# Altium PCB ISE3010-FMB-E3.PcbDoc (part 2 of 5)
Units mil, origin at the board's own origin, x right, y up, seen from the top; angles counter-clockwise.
Board outline 7874.02 x 2362.2 mil, 4 copper layers (Top Layer, MidLayer1, MidLayer2, Bottom Layer), stack 55.6 mil thick; 507 components, 331 nets, 1707 pads, 610 vias.
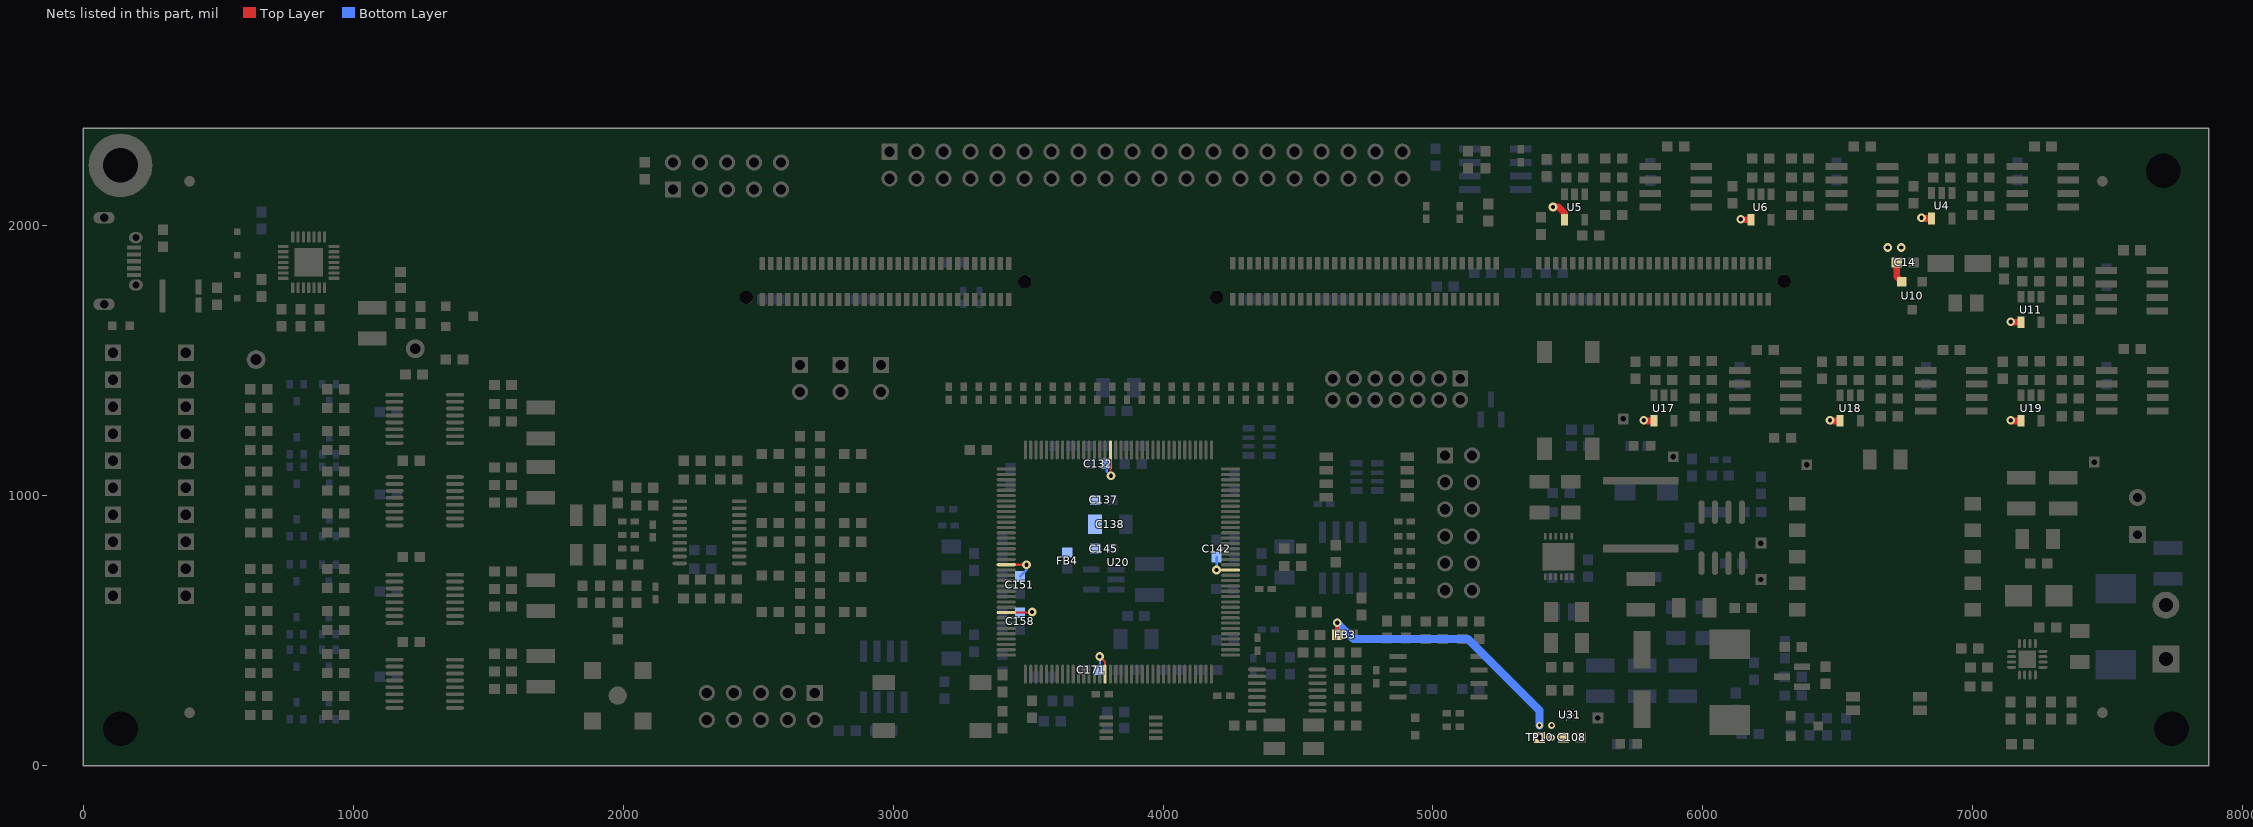
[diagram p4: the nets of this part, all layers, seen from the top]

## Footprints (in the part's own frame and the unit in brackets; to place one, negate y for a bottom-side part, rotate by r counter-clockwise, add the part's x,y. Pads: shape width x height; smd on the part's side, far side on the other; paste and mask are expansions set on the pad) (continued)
HE_800x1150 [mm] "NICHICON"
  rect 1.6x1.6 hole 0.838: 1(-1.75,0)
  round 1.6 hole 0.838: 2(1.75,0)
  silkscreen extent -4.25,-4.25 4.25,4.25, body extent -4.22,-4.24 4.24,4.24, height 11.51
HEADER_2X5 [mil]
  rect 60x60 hole 38: 1(0,0)
  round 60 hole 38: 2(0,100) 3(100,0) 4(100,100) 5(200,0) 6(200,100) 7(300,0) 8(300,100) 9(400,0) 10(400,100)
  silkscreen extent -50,-50 450,150
HEADER_2X6 [mil]
  rect 60x60 hole 38: 1(0,0)
  round 60 hole 38: 2(0,100) 3(100,0) 4(100,100) 5(200,0) 6(200,100) 7(300,0) 8(300,100) 9(400,0) 10(400,100) 11(500,0) 12(500,100)
  silkscreen extent -65,-65 565,165
HSEC8-130-01-L-DV-A [mm]
  rect 0.5x1.2 smd: 121(11.6,1.7) 122(11.6,-1.7) 123(10.8,1.7) 124(10.8,-1.7) 125(10,1.7) 126(10,-1.7) 127(9.2,1.7) 128(9.2,-1.7) 129(8.4,1.7) 130(8.4,-1.7) 131(7.6,1.7) 132(7.6,-1.7) 133(6.8,1.7) 134(6.8,-1.7) 135(6,1.7) 136(6,-1.7) 137(5.2,1.7) 138(5.2,-1.7) 139(4.4,1.7) 140(4.4,-1.7) 141(3.6,1.7) 142(3.6,-1.7) 143(2.8,1.7) 144(2.8,-1.7) 145(2,1.7) 146(2,-1.7) 147(1.2,1.7) 148(1.2,-1.7) 149(0.4,1.7) 150(0.4,-1.7) 151(-0.4,1.7) 152(-0.4,-1.7) 153(-1.2,1.7) 154(-1.2,-1.7) 155(-2,1.7) 156(-2,-1.7) 157(-2.8,1.7) 158(-2.8,-1.7) 159(-3.6,1.7) 160(-3.6,-1.7) 161(-4.4,1.7) 162(-4.4,-1.7) 163(-5.2,1.7) 164(-5.2,-1.7) 165(-6,1.7) 166(-6,-1.7) 167(-6.8,1.7) 168(-6.8,-1.7) 169(-7.6,1.7) 170(-7.6,-1.7) 171(-8.4,1.7) 172(-8.4,-1.7) 173(-9.2,1.7) 174(-9.2,-1.7) 175(-10,1.7) 176(-10,-1.7) 177(-10.8,1.7) 178(-10.8,-1.7) 179(-11.6,1.7) 180(-11.6,-1.7)
  round 1.27 hole 1.27 unplated mask+0.127: 181(13.1,0) 182(-13.1,-1.5)
  silkscreen extent -14.3,-3.55 14.3,3.5
HSEC8-160-01-L-DV-A-L [mm] "CONN HIGH SPD CARD EDGE 120 POS"
  rect 0.5x1.2 smd: 1(25.2,1.7) 2(25.2,-1.7) 3(24.4,1.7) 4(24.4,-1.7) 5(23.6,1.7) 6(23.6,-1.7) 7(22.8,1.7) 8(22.8,-1.7) 9(22,1.7) 10(22,-1.7) 11(21.2,1.7) 12(21.2,-1.7) 13(20.4,1.7) 14(20.4,-1.7) 15(19.6,1.7) 16(19.6,-1.7) 17(18.8,1.7) 18(18.8,-1.7) 19(18,1.7) 20(18,-1.7) 21(17.2,1.7) 22(17.2,-1.7) 23(16.4,1.7) 24(16.4,-1.7) 25(15.6,1.7) 26(15.6,-1.7) 27(14.8,1.7) 28(14.8,-1.7) 29(14,1.7) 30(14,-1.7) 31(13.2,1.7) 32(13.2,-1.7) 33(12.4,1.7) 34(12.4,-1.7) 35(11.6,1.7) 36(11.6,-1.7) 37(10.8,1.7) 38(10.8,-1.7) 39(10,1.7) 40(10,-1.7) 41(9.2,1.7) 42(9.2,-1.7) 43(8.4,1.7) 44(8.4,-1.7) 45(7.6,1.7) 46(7.6,-1.7) 47(6.8,1.7) 48(6.8,-1.7) 49(6,1.7) 50(6,-1.7) 51(5.2,1.7) 52(5.2,-1.7) 53(4.4,1.7) 54(4.4,-1.7) 55(3.6,1.7) 56(3.6,-1.7) 57(-0.4,1.7) 58(-0.4,-1.7) 59(-1.2,1.7) 60(-1.2,-1.7) 61(-2,1.7) 62(-2,-1.7) 63(-2.8,1.7) 64(-2.8,-1.7) 65(-3.6,1.7) 66(-3.6,-1.7) 67(-4.4,1.7) 68(-4.4,-1.7) 69(-5.2,1.7) 70(-5.2,-1.7) 71(-6,1.7) 72(-6,-1.7) 73(-6.8,1.7) 74(-6.8,-1.7) 75(-7.6,1.7) 76(-7.6,-1.7) 77(-8.4,1.7) 78(-8.4,-1.7) 79(-9.2,1.7) 80(-9.2,-1.7) 81(-10,1.7) 82(-10,-1.7) 83(-10.8,1.7) 84(-10.8,-1.7) 85(-11.6,1.7) 86(-11.6,-1.7) 87(-12.4,1.7) 88(-12.4,-1.7) 89(-13.2,1.7) 90(-13.2,-1.7) 91(-14,1.7) 92(-14,-1.7) 93(-14.8,1.7) 94(-14.8,-1.7) 95(-15.6,1.7) 96(-15.6,-1.7) 97(-16.4,1.7) 98(-16.4,-1.7) 99(-17.2,1.7) 100(-17.2,-1.7) 101(-18,1.7) 102(-18,-1.7) 103(-18.8,1.7) 104(-18.8,-1.7) 105(-19.6,1.7) 106(-19.6,-1.7) 107(-20.4,1.7) 108(-20.4,-1.7) 109(-21.2,1.7) 110(-21.2,-1.7) 111(-22,1.7) 112(-22,-1.7) 113(-22.8,1.7) 114(-22.8,-1.7) 115(-23.6,1.7) 116(-23.6,-1.7) 117(-24.4,1.7) 118(-24.4,-1.7) 119(-25.2,1.7) 120(-25.2,-1.7)
  round 1.27 hole 1.27 unplated mask+0.127: 121(-26.7,-1.5) 122(26.7,0)
  silkscreen extent -35.4,-3.56 35.4,3.5
Label_650x200 [mil] "Thermal Transfer Label"
  silkscreen extent -325,-100 325,100, body extent -326,-101 326,101, height 1
LED0603AA [mil]
  rect 32x32 smd: 1(-32.48,0) 2(32.48,0)
  silkscreen extent -132,-25 8,25
LED_0603 [mm] "LED, HIGHBRIGHT, BLUE, SMT0603"
  rect 0.9x0.9 smd paste+0: 1(-0.8,0) 2(0.8,0)
  silkscreen extent -0.81,-0.76 1.65,0.76, body extent -0.8,-0.4 0.8,0.4, height 0.8
MF05A_N [mm] "SOT23, 5-Leads, Body 2.9x1.6mm, Pitch 0.95mm, Lead Span 2.8mm, IPC Medium Density"
  rect 1.1x0.65 smd: 1(-1.2,0.95) 2(-1.2,0) 3(-1.2,-0.95) 4(1.2,-0.95) 5(1.2,0.95)
  silkscreen extent -1.32,-1.55 0.25,1.8, body extent -0.9,-1.55 0.9,1.55, height 1.19
MH3.2 [mm]
  round 6 / inner round 3.607 / far side round 6 hole 3.251: 1(0,0)
  silkscreen extent -3.25,-3.25 3.25,3.25
MH3.2_NPTH [mil]
  round 20 / inner round 142 / far side round 20 hole 128 unplated mask+65: 1(0,0)
  silkscreen extent -120,-120 120,120
MSS7341 [mil] "Coilcraft recommended land pattern Document 383-2 1/3/11"
  rect 28.54x280 smd: 1(-125.49,0) 2(125.49,0)
  Top Layer region: -41.34,-139.76 -41.34,-101.16 -41.33,-101.13 -82.83,-71.24 -106.18,-25.72 -106.25,25.43 -83.02,71.01 -41.6,101.02 -41.6,101.02 -41.34,101.02 -41.34,139.76 -139.76,139.76 -139.76,-139.76
  Top Layer region: 41.34,-139.76 41.34,-101.16 41.33,-101.13 82.83,-71.24 106.18,-25.72 106.25,25.43 83.02,71.01 41.6,101.02 41.6,101.02 41.34,101.02 41.34,139.76 139.76,139.76 139.76,-139.76
  silkscreen extent -152,-154 151,154, body extent -149,-149 149,149, height 162
"POLYZEN 4 x 4 SMD" [mm] "POLYZEN 4 x 4 SMD"
  rect 0.56x3.1 smd: 1(-1.7,0)
  rect 0.56x1.4 smd: 2(1.7,0.85) 3(1.7,-0.85)
  silkscreen extent -2.3,-2.3 2.3,2.3
PW0014A_N [mm] "TSOP, 14-Leads, Body 5x4.4mm, Pitch 0.65mm, IPC Medium Density"
  oval 1.7x0.35 smd: 1(-2.85,1.95) 2(-2.85,1.3) 3(-2.85,0.65) 4(-2.85,0) 5(-2.85,-0.65) 6(-2.85,-1.3) 7(-2.85,-1.95) 8(2.85,-1.95) 9(2.85,-1.3) 10(2.85,-0.65) 11(2.85,0) 12(2.85,0.65) 13(2.85,1.3) 14(2.85,1.95)
  silkscreen extent -1.7,-2.55 1.7,2.29, body extent -3.21,-2.5 3.21,2.5, height 0.98
PW0016A_N [mm] "TSOP, 16-Leads, Body 5x4.4mm, Pitch 0.65mm, IPC Medium Density"
  oval 1.7x0.35 smd: 1(-2.85,2.275) 2(-2.85,1.625) 3(-2.85,0.975) 4(-2.85,0.325) 5(-2.85,-0.325) 6(-2.85,-0.975) 7(-2.85,-1.625) 8(-2.85,-2.275) 9(2.85,-2.275) 10(2.85,-1.625) 11(2.85,-0.975) 12(2.85,-0.325) 13(2.85,0.325) 14(2.85,0.975) 15(2.85,1.625) 16(2.85,2.275)
  silkscreen extent -1.5,-2.55 1.5,2.55, body extent -3.21,-2.5 3.21,2.5, height 0.98
PW0020A_L [mm] "TSOP, 20-Leads, Body 6.5x4.4mm, Pitch 0.65mm, IPC High Density"
  oval 1.4x0.35 smd: 1(-2.8,2.925) 2(-2.8,2.275) 3(-2.8,1.625) 4(-2.8,0.975) 5(-2.8,0.325) 6(-2.8,-0.325) 7(-2.8,-0.975) 8(-2.8,-1.625) 9(-2.8,-2.275) 10(-2.8,-2.925) 11(2.8,-2.925) 12(2.8,-2.275) 13(2.8,-1.625) 14(2.8,-0.975) 15(2.8,-0.325) 16(2.8,0.325) 17(2.8,0.975) 18(2.8,1.625) 19(2.8,2.275) 20(2.8,2.925)
  silkscreen extent -2.92,-3.3 1.7,3.77, body extent -2.25,-3.3 2.25,3.3, height 1.2
QFN28[RHD] [mil]
  rrect50% 11.8x40 smd mask+2: 1(-59.1,-94) 2(-39.4,-94) 3(-19.7,-94) 4(0,-94) 5(19.7,-94) 6(39.4,-94) 7(59.1,-94) 15(59.1,94) 16(39.4,94) 17(19.7,94) 18(0,94) 19(-19.7,94) 20(-39.4,94) 21(-59.1,94)
  rrect50% 40x11.8 smd mask+2: 8(94,-59.1) 9(94,-39.4) 10(94,-19.7) 11(94,0) 12(94,19.7) 13(94,39.4) 14(94,59.1) 22(-94,59.1) 23(-94,39.4) 24(-94,19.7) 25(-94,0) 26(-94,-19.7) 27(-94,-39.4) 28(-94,-59.1)
  rect 106x106 smd mask+2.5: 29(0,0)
  silkscreen extent -164,-122 -139,-97
R-ACAS_0612 [mil]
  rect 25x45 smd mask+2.5: 1(-50.5,38.5) 2(-50.5,-38.5) 7(50.5,38.5) 8(50.5,-38.5)
  rect 17x45 smd mask+2.5: 3(-15.5,38.5) 4(-15.5,-38.5) 5(15.5,38.5) 6(15.5,-38.5)
RTE0016C [mm] "Texas Insturments"
  oval 0.85x0.28 smd mask+0.064: 1(-1.475,0.75) 2(-1.475,0.25) 3(-1.475,-0.25) 4(-1.475,-0.75) 9(1.475,-0.75) 10(1.475,-0.25) 11(1.475,0.25) 12(1.475,0.75)
  oval 0.28x0.85 smd mask+0.064: 5(-0.75,-1.475) 6(-0.25,-1.475) 7(0.25,-1.475) 8(0.75,-1.475) 13(0.75,1.475) 14(0.25,1.475) 15(-0.25,1.475) 16(-0.75,1.475)
  rect 1.66x1.66 smd paste-0.88 mask+0.089: 17(0,0)
  silkscreen extent -2.3,-1.78 1.78,1.78, body extent -1.58,-1.58 1.58,1.58, height 0.81
SM_RADIAL_6.3BMM [mm] "Nichicon 6.3x7.7"
  rect 3.5x1.6 smd: 1(-2.8,0) 2(2.8,0)
  silkscreen extent -3.4,-3.4 3.4,3.4, body extent -3.41,-3.41 3.41,3.41, height 8
SM_RADIAL_B [mm] "4 x 5.8mm:  Panasonic B"
  rect 2.5x1.6 smd: 1(-1.75,0) 2(1.75,0)
  silkscreen extent -2.24,-2.25 2.25,2.25, body extent -2.26,-2.26 2.26,2.26, height 6.1
SMA [mm] "Molded Diode, 2-Leads, Body 4.3x2.6mm, IPC Medium Density, based on OnSemi component dimensions and land pattern"
  rect 2x2 smd: 1(-2,0) 2(2,0)
  silkscreen extent -3.66,-1.57 2.79,1.57, body extent -2.6,-1.3 2.6,1.3, height 2.42
SMC [mil] "Molded Diode, 2-Leads, Body 6.9x5.8mm, IPC Medium Density, based on OnSemi component dimensions and land patterns"
  rect 110x150 smd: 1(-140.49,0) 2(140.49,0)
  silkscreen extent -221,-124 189,123, body extent -156,-116 156,116, height 91
SO8 [mil]
  rect 80x26 smd: 1(-95,75) 2(-95,25) 3(-95,-25) 4(-95,-75) 5(94,-75) 6(94,-25) 7(94,25) 8(94,75)
  silkscreen extent -160,115 -120,155
SO8W [mm] "SO8W P 7.62mm X 1.27"
  rect 1.6x0.5 smd: 1(0,0) 2(0,-1.27) 3(0,-2.54) 4(0,-3.81) 5(7.62,-3.81) 6(7.62,-2.54) 7(7.62,-1.27) 8(7.62,0)
  silkscreen extent -1.67,-4.44 8.7,0.72
sod-323 [mm] "NXP recommended land pattern"
  rect 0.6x0.6 smd: 1(-1.1,0) 2(1.1,0)
  silkscreen extent -2.06,-0.86 1.53,0.86, body extent -1.3,-0.67 1.3,0.68, height 1.1
SOP-4 [mm] "Vishay Half Pitch Mini-Flat Package"
  rect 1.3x0.9 smd: 1(-3.15,0.635) 2(-3.15,-0.635) 3(3.15,-0.635) 4(3.15,0.635)
  silkscreen extent -2.2,-1.41 2.2,1.39, body extent -3.5,-1.4 3.5,1.4, height 2.12
SOT-23#1 [mm] "SOT23, 3-Leads, Body 2.9x1.3mm, Pitch 0.95mm, Lead Span 2.5mm, IPC Medium Density"
  rect 1.5x0.6 smd: 1(-0.95,0.95) 2(-0.95,-0.95) 3(0.95,0)
  silkscreen extent 0.2,-1.5 0.7,1.5, body extent -1.16,-1.45 1.21,1.45, height 1
SOT-23#2 [mm]
  rect 0.889x0.889 smd: 1(-0.952,-1.334) 2(0.953,-1.333) 3(0,1.27)
SOT-323 [mm] "Zetex recommended land pattern.  March 2007"
  rect 0.8x0.6 smd: 1(-0.8,0.65) 2(-0.8,-0.65) 3(0.8,0)
  silkscreen extent -1.14,-1.22 1.09,1.49, body extent -1.13,-1.13 1.12,1.12, height 1.13
SW_218-4LPST [mil] "CTS Components"
  rect 50x30 smd: 1(-150,75) 2(-150,25) 3(-150,-25) 4(-150,-75) 5(150,-75) 6(150,-25) 7(150,25) 8(150,75)
  silkscreen extent -114,-123 114,123, body extent -166,-123 166,123, height 104
SW_FSM4JSMA [mm] "Alcoswitch"
  rect 1.4x2.1 smd: 1(2.25,4.55) 2(2.25,-4.55) 3(-2.25,4.55) 4(-2.25,-4.55)
  silkscreen extent -3,-3 3,3, body extent -3,-5 3,5, height 5.1
TB_2X5.1MM [mil]
  rect 100x100 hole 52: 1(0,0)
  round 100 hole 52: 2(200,0)
TI_Stacked_SolderMask_Small [mil]
  rect 0x0 smd paste-125 mask-125: 0(0,0)
  Top Layer region: 519 vertices and 0 holes, not listed, extent -418.39,-77.79 -237.37,98.14
  Top Layer region: -289.71,63.25 -290.44,63.25 -290.44,59.61 -291.16,59.61 -291.16,55.98 -291.89,55.98 -291.89,52.34 -292.62,52.34 -292.62,48.71 -293.34,48.71 -293.34,45.07 -294.07,45.07 -294.07,41.44 -294.8,41.44 -294.8,37.8 -295.53,37.8 -295.53,34.17 -296.25,34.17 -296.25,30.53 -296.98,30.53 -296.98,26.9 -297.71,26.9 -297.71,23.26 -298.43,23.26 -298.43,19.63 -299.16,19.63 -299.16,15.99 -299.89,15.99 -299.89,12.36 -300.61,12.36 -300.61,8.72 -301.34,8.72 -301.34,5.09 -302.07,5.09 -302.07,1.45 -302.8,1.45 -302.8,-2.18 -303.52,-2.18 -303.52,-5.82 -304.25,-5.82 -304.25,-9.45 -321.7,-9.45 -321.7,-7.27 -320.97,-7.27 -320.97,-3.64 -320.24,-3.64 -320.24,0 -319.52,0 -319.52,3.64 -318.79,3.64 -318.79,7.27 -318.06,7.27 -318.06,10.91 -317.34,10.91 -317.34,14.54 -316.61,14.54 -316.61,18.18 -315.88,18.18 -315.88,21.81 -315.15,21.81 -315.15,25.45 -314.43,25.45 -314.43,29.08 -313.7,29.08 -313.7,32.72 -312.97,32.72 -312.97,36.35 -312.25,36.35 -312.25,39.99 -311.52,39.99 -311.52,43.62 -310.79,43.62 -310.79,47.26 -310.07,47.26 -310.07,50.89 -309.34,50.89 -309.34,54.53 -308.61,54.53 -308.61,58.16 -307.88,58.16 -307.88,61.8 -307.16,61.8 -307.16,64.7 -289.71,64.7
  Top Layer region: 537 vertices and 1 holes, not listed, extent -104.32,-10.18 14.18,47.26
  Top Layer region: 271 vertices and 0 holes, not listed, extent 124.68,-98.14 197.38,-39.99
  Top Layer region: 193 vertices and 1 holes, not listed, extent 3.27,-98.14 65.79,-39.99
  Top Layer region: 243 vertices and 0 holes, not listed, extent -158.85,-98.14 -100.69,-39.99
  Top Layer region: 249 vertices and 0 holes, not listed, extent 255.54,-98.14 313.7,-39.99
  Top Layer region: -145.76,62.52 -145.04,62.52 -145.04,60.34 -144.31,60.34 -144.31,58.16 -143.58,58.16 -143.58,55.98 -142.86,55.98 -142.86,53.8 -142.13,53.8 -142.13,51.62 -141.4,51.62 -141.4,50.89 -142.13,50.89 -142.13,50.16 -143.58,50.16 -143.58,51.62 -144.31,51.62 -144.31,52.34 -145.04,52.34 -145.04,53.07 -145.76,53.07 -145.76,53.8 -147.22,53.8 -147.22,54.53 -147.94,54.53 -147.94,55.25 -150.13,55.25 -150.13,55.98 -153.03,55.98 -153.03,56.71 -168.3,56.71 -168.3,55.98 -169.03,55.98 -169.03,54.53 -169.75,54.53 -169.75,-2.91 -169.03,-2.91 -169.03,-5.09 -168.3,-5.09 -168.3,-5.82 -167.57,-5.82 -167.57,-6.54 -166.85,-6.54 -166.85,-7.27 -165.39,-7.27 -165.39,-8 -163.94,-8 -163.94,-10.18 -188.66,-10.18 -188.66,-8 -187.2,-8 -187.2,-7.27 -185.75,-7.27 -185.75,-6.54 -185.02,-6.54 -185.02,-5.82 -184.29,-5.82 -184.29,-5.09 -183.57,-5.09 -183.57,-2.18 -182.84,-2.18 -182.84,53.8 -183.57,53.8 -183.57,55.98 -185.02,55.98 -185.02,56.71 -199.56,56.71 -199.56,55.98 -202.47,55.98 -202.47,55.25 -204.65,55.25 -204.65,54.53 -205.38,54.53 -205.38,53.8 -206.83,53.8 -206.83,53.07 -207.56,53.07 -207.56,52.34 -208.29,52.34 -208.29,51.62 -209.01,51.62 -209.01,50.89 -209.74,50.89 -209.74,50.16 -210.47,50.16 -210.47,50.89 -211.19,50.89 -211.19,53.07 -210.47,53.07 -210.47,54.53 -209.74,54.53 -209.74,56.71 -209.01,56.71 -209.01,58.89 -208.29,58.89 -208.29,61.07 -207.56,61.07 -207.56,63.25 -206.83,63.25 -206.83,64.7 -145.76,64.7
  Top Layer region: 246.82,-41.44 247.54,-41.44 247.54,-42.89 248.27,-42.89 248.27,-45.07 249,-45.07 249,-47.26 249.72,-47.26 249.72,-48.71 250.45,-48.71 250.45,-50.89 251.18,-50.89 251.18,-53.07 250.45,-53.07 250.45,-53.8 249.72,-53.8 249.72,-53.07 249,-53.07 249,-52.34 248.27,-52.34 248.27,-51.62 246.82,-51.62 246.82,-50.89 246.09,-50.89 246.09,-50.16 245.36,-50.16 245.36,-49.44 244.64,-49.44 244.64,-48.71 243.18,-48.71 243.18,-47.98 241,-47.98 241,-47.26 238.09,-47.26 238.09,-46.53 222.83,-46.53 222.83,-47.26 220.64,-47.26 220.64,-48.71 219.92,-48.71 219.92,-63.98 237.37,-63.98 237.37,-63.25 239.55,-63.25 239.55,-62.52 240.27,-62.52 240.27,-61.8 241,-61.8 241,-60.34 241.73,-60.34 241.73,-58.89 243.91,-58.89 243.91,-74.88 241.73,-74.88 241.73,-73.43 241,-73.43 241,-71.97 240.27,-71.97 240.27,-71.25 238.09,-71.25 238.09,-70.52 219.92,-70.52 219.92,-88.69 220.64,-88.69 220.64,-90.15 241.73,-90.15 241.73,-89.42 244.64,-89.42 244.64,-88.69 246.09,-88.69 246.09,-87.97 247.54,-87.97 247.54,-87.24 248.27,-87.24 248.27,-86.51 249,-86.51 249,-85.79 249.72,-85.79 249.72,-85.06 250.45,-85.06 250.45,-84.33 251.18,-84.33 251.18,-83.61 251.91,-83.61 251.91,-82.88 253.36,-82.88 253.36,-83.61 254.09,-83.61 254.09,-85.06 253.36,-85.06 253.36,-86.51 252.63,-86.51 252.63,-88.69 251.91,-88.69 251.91,-90.15 251.18,-90.15 251.18,-92.33 250.45,-92.33 250.45,-93.78 249.72,-93.78 249.72,-95.96 249,-95.96 249,-97.42 201.74,-97.42 201.74,-95.24 203.2,-95.24 203.2,-94.51 204.65,-94.51 204.65,-93.78 206.1,-93.78 206.1,-93.06 206.83,-93.06 206.83,-90.88 207.56,-90.88 207.56,-45.8 206.83,-45.8 206.83,-44.35 206.1,-44.35 206.1,-43.62 205.38,-43.62 205.38,-42.89 203.92,-42.89 203.92,-42.17 201.74,-42.17 201.74,-39.99 246.82,-39.99
  Top Layer region: -110.14,45.8 -109.41,45.8 -109.41,44.35 -108.69,44.35 -108.69,42.17 -107.96,42.17 -107.96,39.99 -107.23,39.99 -107.23,37.8 -106.51,37.8 -106.51,36.35 -105.78,36.35 -105.78,33.44 -107.96,33.44 -107.96,34.17 -108.69,34.17 -108.69,34.9 -109.41,34.9 -109.41,35.62 -110.14,35.62 -110.14,36.35 -110.87,36.35 -110.87,37.08 -111.59,37.08 -111.59,37.8 -113.05,37.8 -113.05,38.53 -114.5,38.53 -114.5,39.26 -116.68,39.26 -116.68,39.99 -135.59,39.99 -135.59,39.26 -136.31,39.26 -136.31,38.53 -137.04,38.53 -137.04,23.26 -118.14,23.26 -118.14,23.99 -116.68,23.99 -116.68,24.72 -115.96,24.72 -115.96,26.17 -115.23,26.17 -115.23,27.63 -113.05,27.63 -113.05,11.63 -115.23,11.63 -115.23,13.81 -115.96,13.81 -115.96,14.54 -116.68,14.54 -116.68,15.27 -117.41,15.27 -117.41,15.99 -119.59,15.99 -119.59,16.72 -137.04,16.72 -137.04,-1.45 -136.31,-1.45 -136.31,-2.91 -134.13,-2.91 -134.13,-3.64 -118.86,-3.64 -118.86,-2.91 -113.78,-2.91 -113.78,-2.18 -111.59,-2.18 -111.59,-1.45 -110.14,-1.45 -110.14,-0.73 -109.41,-0.73 -109.41,0 -107.96,0 -107.96,0.73 -107.23,0.73 -107.23,1.45 -106.51,1.45 -106.51,2.18 -105.78,2.18 -105.78,2.91 -105.05,2.91 -105.05,3.64 -104.32,3.64 -104.32,4.36 -103.6,4.36 -103.6,3.64 -102.87,3.64 -102.87,2.18 -103.6,2.18 -103.6,0 -104.32,0 -104.32,-1.45 -105.05,-1.45 -105.05,-3.64 -105.78,-3.64 -105.78,-5.09 -106.51,-5.09 -106.51,-7.27 -107.23,-7.27 -107.23,-8.72 -107.96,-8.72 -107.96,-10.18 -155.21,-10.18 -155.21,-8 -153.03,-8 -153.03,-7.27 -151.58,-7.27 -151.58,-6.54 -150.85,-6.54 -150.85,-5.82 -150.13,-5.82 -150.13,-4.36 -149.4,-4.36 -149.4,41.44 -150.13,41.44 -150.13,42.89 -150.85,42.89 -150.85,43.62 -151.58,43.62 -151.58,44.35 -153.76,44.35 -153.76,45.07 -155.21,45.07 -155.21,47.26 -110.14,47.26
  Top Layer region: 293 vertices and 0 holes, not listed, extent 12,-10.91 59.25,47.98
  Top Layer region: 295 vertices and 0 holes, not listed, extent -98.51,-98.14 -51.25,-39.26
  Top Layer region: 283 vertices and 0 holes, not listed, extent 371.13,-98.14 418.39,-39.26
  Top Layer region: 121.05,-42.17 118.86,-42.17 118.86,-42.89 118.14,-42.89 118.14,-43.62 117.41,-43.62 117.41,-44.35 116.68,-44.35 116.68,-45.8 115.96,-45.8 115.96,-82.15 115.23,-82.15 115.23,-85.79 114.5,-85.79 114.5,-87.24 113.78,-87.24 113.78,-88.69 113.05,-88.69 113.05,-90.15 112.32,-90.15 112.32,-90.88 111.59,-90.88 111.59,-92.33 110.87,-92.33 110.87,-93.06 110.14,-93.06 110.14,-93.78 108.69,-93.78 108.69,-94.51 107.96,-94.51 107.96,-95.24 106.51,-95.24 106.51,-95.96 104.32,-95.96 104.32,-96.69 102.14,-96.69 102.14,-97.42 97.78,-97.42 97.78,-98.14 86.15,-98.14 86.15,-97.42 81.79,-97.42 81.79,-96.69 79.61,-96.69 79.61,-95.96 77.43,-95.96 77.43,-95.24 75.97,-95.24 75.97,-94.51 74.52,-94.51 74.52,-93.78 73.79,-93.78 73.79,-93.06 72.34,-93.06 72.34,-92.33 71.61,-92.33 71.61,-91.6 70.88,-91.6 70.88,-90.88 70.16,-90.88 70.16,-90.15 69.43,-90.15 69.43,-88.69 68.7,-88.69 68.7,-87.97 67.97,-87.97 67.97,-86.51 67.25,-86.51 67.25,-84.33 66.52,-84.33 66.52,-47.26 65.79,-47.26 65.79,-45.07 65.07,-45.07 65.07,-43.62 64.34,-43.62 64.34,-42.89 62.89,-42.89 62.89,-42.17 60.7,-42.17 60.7,-39.99 83.97,-39.99 83.97,-42.17 81.79,-42.17 81.79,-42.89 80.33,-42.89 80.33,-43.62 79.61,-43.62 79.61,-45.07 78.88,-45.07 78.88,-47.98 78.15,-47.98 78.15,-79.24 78.88,-79.24 78.88,-82.88 79.61,-82.88 79.61,-85.06 80.33,-85.06 80.33,-86.51 81.06,-86.51 81.06,-87.24 81.79,-87.24 81.79,-87.97 82.51,-87.97 82.51,-88.69 83.97,-88.69 83.97,-89.42 85.42,-89.42 85.42,-90.15 88.33,-90.15 88.33,-90.88 98.51,-90.88 98.51,-90.15 101.42,-90.15 101.42,-89.42 102.87,-89.42 102.87,-88.69 103.6,-88.69 103.6,-87.97 104.32,-87.97 104.32,-87.24 105.05,-87.24 105.05,-86.51 105.78,-86.51 105.78,-85.79 106.51,-85.79 106.51,-83.61 107.23,-83.61 107.23,-80.7 107.96,-80.7 107.96,-47.26 107.23,-47.26 107.23,-45.07 106.51,-45.07 106.51,-43.62 105.78,-43.62 105.78,-42.89 104.32,-42.89 104.32,-42.17 102.14,-42.17 102.14,-39.99 121.05,-39.99
  Top Layer region: -1.82,-42.17 -1.09,-42.17 -1.09,-45.07 -0.36,-45.07 -0.36,-47.26 0.36,-47.26 0.36,-49.44 1.09,-49.44 1.09,-51.62 1.82,-51.62 1.82,-55.25 0.36,-55.25 0.36,-54.53 -0.36,-54.53 -0.36,-53.8 -1.09,-53.8 -1.09,-53.07 -1.82,-53.07 -1.82,-52.34 -2.54,-52.34 -2.54,-51.62 -3.27,-51.62 -3.27,-50.89 -4,-50.89 -4,-50.16 -4.73,-50.16 -4.73,-49.44 -5.45,-49.44 -5.45,-48.71 -6.18,-48.71 -6.18,-47.98 -8.36,-47.98 -8.36,-47.26 -11.27,-47.26 -11.27,-46.53 -17.81,-46.53 -17.81,-47.26 -18.54,-47.26 -18.54,-47.98 -19.27,-47.98 -19.27,-90.88 -18.54,-90.88 -18.54,-93.06 -17.81,-93.06 -17.81,-93.78 -16.36,-93.78 -16.36,-94.51 -14.18,-94.51 -14.18,-95.24 -12.72,-95.24 -12.72,-97.42 -37.44,-97.42 -37.44,-95.24 -36.71,-95.24 -36.71,-94.51 -34.53,-94.51 -34.53,-93.78 -33.08,-93.78 -33.08,-93.06 -32.35,-93.06 -32.35,-91.6 -31.62,-91.6 -31.62,-47.26 -33.08,-47.26 -33.08,-46.53 -39.62,-46.53 -39.62,-47.26 -42.53,-47.26 -42.53,-47.98 -43.98,-47.98 -43.98,-48.71 -44.71,-48.71 -44.71,-49.44 -46.16,-49.44 -46.16,-50.16 -46.89,-50.16 -46.89,-50.89 -47.62,-50.89 -47.62,-52.34 -48.35,-52.34 -48.35,-53.07 -49.07,-53.07 -49.07,-53.8 -49.8,-53.8 -49.8,-54.53 -50.53,-54.53 -50.53,-55.25 -51.98,-55.25 -51.98,-54.53 -52.71,-54.53 -52.71,-53.8 -51.98,-53.8 -51.98,-51.62 -51.25,-51.62 -51.25,-49.44 -50.53,-49.44 -50.53,-47.26 -49.8,-47.26 -49.8,-44.35 -49.07,-44.35 -49.07,-42.17 -48.35,-42.17 -48.35,-39.99 -1.82,-39.99
  Top Layer region: -163.21,-23.99 -163.94,-23.99 -163.94,-24.72 -166.12,-24.72 -166.12,-25.45 -167.57,-25.45 -167.57,-26.17 -168.3,-26.17 -168.3,-26.9 -169.03,-26.9 -169.03,-29.08 -169.75,-29.08 -169.75,-90.15 -169.03,-90.15 -169.03,-92.33 -168.3,-92.33 -168.3,-93.06 -167.57,-93.06 -167.57,-93.78 -166.12,-93.78 -166.12,-94.51 -163.94,-94.51 -163.94,-95.24 -163.21,-95.24 -163.21,-97.42 -189.38,-97.42 -189.38,-95.24 -188.66,-95.24 -188.66,-94.51 -186.48,-94.51 -186.48,-93.78 -185.02,-93.78 -185.02,-93.06 -184.29,-93.06 -184.29,-91.6 -183.57,-91.6 -183.57,-89.42 -182.84,-89.42 -182.84,-29.81 -183.57,-29.81 -183.57,-27.63 -184.29,-27.63 -184.29,-26.17 -185.75,-26.17 -185.75,-25.45 -186.48,-25.45 -186.48,-24.72 -188.66,-24.72 -188.66,-23.99 -189.38,-23.99 -189.38,-22.54 -163.21,-22.54
  Top Layer region: 364.59,-40.71 365.32,-40.71 365.32,-42.89 366.04,-42.89 366.04,-45.07 366.77,-45.07 366.77,-47.26 367.5,-47.26 367.5,-50.16 368.23,-50.16 368.23,-52.34 368.95,-52.34 368.95,-55.25 366.77,-55.25 366.77,-53.8 366.04,-53.8 366.04,-53.07 365.32,-53.07 365.32,-52.34 364.59,-52.34 364.59,-51.62 363.86,-51.62 363.86,-50.89 363.14,-50.89 363.14,-50.16 362.41,-50.16 362.41,-49.44 361.68,-49.44 361.68,-48.71 360.96,-48.71 360.96,-47.98 358.77,-47.98 358.77,-47.26 355.87,-47.26 355.87,-46.53 349.32,-46.53 349.32,-47.26 348.6,-47.26 348.6,-47.98 347.87,-47.98 347.87,-91.6 348.6,-91.6 348.6,-93.06 349.32,-93.06 349.32,-93.78 350.78,-93.78 350.78,-94.51 352.96,-94.51 352.96,-95.24 353.69,-95.24 353.69,-97.42 329.69,-97.42 329.69,-95.24 330.42,-95.24 330.42,-94.51 332.6,-94.51 332.6,-93.78 334.06,-93.78 334.06,-93.06 334.78,-93.06 334.78,-91.6 335.51,-91.6 335.51,-47.98 334.78,-47.98 334.78,-47.26 334.06,-47.26 334.06,-46.53 327.51,-46.53 327.51,-47.26 324.61,-47.26 324.61,-47.98 323.15,-47.98 323.15,-48.71 321.7,-48.71 321.7,-49.44 320.97,-49.44 320.97,-50.16 320.24,-50.16 320.24,-50.89 319.52,-50.89 319.52,-51.62 318.79,-51.62 318.79,-53.07 318.06,-53.07 318.06,-53.8 317.34,-53.8 317.34,-54.53 316.61,-54.53 316.61,-55.25 315.15,-55.25 315.15,-54.53 314.43,-54.53 314.43,-53.8 315.15,-53.8 315.15,-51.62 315.88,-51.62 315.88,-48.71 316.61,-48.71 316.61,-46.53 317.34,-46.53 317.34,-44.35 318.06,-44.35 318.06,-42.17 318.79,-42.17 318.79,-39.99 364.59,-39.99
  Top Layer region: -285.35,85.79 -286.07,85.79 -286.07,82.15 -286.8,82.15 -286.8,78.52 -287.53,78.52 -287.53,74.88 -288.26,74.88 -288.26,71.97 -305.7,71.97 -305.7,73.43 -304.98,73.43 -304.98,77.06 -304.25,77.06 -304.25,80.7 -303.52,80.7 -303.52,84.33 -302.8,84.33 -302.8,87.97 -302.07,87.97 -302.07,88.69 -285.35,88.69
TP-040_RND [mil]
  round 70 / inner round 62 / far side round 62 hole 40: 1(0,0)
TP-SMALL [mil]
  rect 40x40 hole 20: 1(0,0)
TQG144_N [mm] "Thin QFP, 144-Leads, Body 20x20mm, Pitch 0.5mm, IPC Medium Density"
  oval 1.8x0.3 smd mask+0.051: 1(-10.55,8.75) 2(-10.55,8.25) 3(-10.55,7.75) 4(-10.55,7.25) 5(-10.55,6.75) 6(-10.55,6.25) 7(-10.55,5.75) 8(-10.55,5.25) 9(-10.55,4.75) 10(-10.55,4.25) 11(-10.55,3.75) 12(-10.55,3.25) 13(-10.55,2.75) 14(-10.55,2.25) 15(-10.55,1.75) 16(-10.55,1.25) 17(-10.55,0.75) 18(-10.55,0.25) 19(-10.55,-0.25) 20(-10.55,-0.75) 21(-10.55,-1.25) 22(-10.55,-1.75) 23(-10.55,-2.25) 24(-10.55,-2.75) 25(-10.55,-3.25) 26(-10.55,-3.75) 27(-10.55,-4.25) 28(-10.55,-4.75) 29(-10.55,-5.25) 30(-10.55,-5.75) 31(-10.55,-6.25) 32(-10.55,-6.75) 33(-10.55,-7.25) 34(-10.55,-7.75) 35(-10.55,-8.25) 36(-10.55,-8.75) 73(10.55,-8.75) 74(10.55,-8.25) 75(10.55,-7.75) 76(10.55,-7.25) 77(10.55,-6.75) 78(10.55,-6.25) 79(10.55,-5.75) 80(10.55,-5.25) 81(10.55,-4.75) 82(10.55,-4.25) 83(10.55,-3.75) 84(10.55,-3.25) 85(10.55,-2.75) 86(10.55,-2.25) 87(10.55,-1.75) 88(10.55,-1.25) 89(10.55,-0.75) 90(10.55,-0.25) 91(10.55,0.25) 92(10.55,0.75) 93(10.55,1.25) 94(10.55,1.75) 95(10.55,2.25) 96(10.55,2.75) 97(10.55,3.25) 98(10.55,3.75) 99(10.55,4.25) 100(10.55,4.75) 101(10.55,5.25) 102(10.55,5.75) 103(10.55,6.25) 104(10.55,6.75) 105(10.55,7.25) 106(10.55,7.75) 107(10.55,8.25) 108(10.55,8.75)
  oval 0.3x1.8 smd mask+0.051: 37(-8.75,-10.55) 38(-8.25,-10.55) 39(-7.75,-10.55) 40(-7.25,-10.55) 41(-6.75,-10.55) 42(-6.25,-10.55) 43(-5.75,-10.55) 44(-5.25,-10.55) 45(-4.75,-10.55) 46(-4.25,-10.55) 47(-3.75,-10.55) 48(-3.25,-10.55) 49(-2.75,-10.55) 50(-2.25,-10.55) 51(-1.75,-10.55) 52(-1.25,-10.55) 53(-0.75,-10.55) 54(-0.25,-10.55) 55(0.25,-10.55) 56(0.75,-10.55) 57(1.25,-10.55) 58(1.75,-10.55) 59(2.25,-10.55) 60(2.75,-10.55) 61(3.25,-10.55) 62(3.75,-10.55) 63(4.25,-10.55) 64(4.75,-10.55) 65(5.25,-10.55) 66(5.75,-10.55) 67(6.25,-10.55) 68(6.75,-10.55) 69(7.25,-10.55) 70(7.75,-10.55) 71(8.25,-10.55) 72(8.75,-10.55) 109(8.75,10.55) 110(8.25,10.55) 111(7.75,10.55) 112(7.25,10.55) 113(6.75,10.55) 114(6.25,10.55) 115(5.75,10.55) 116(5.25,10.55) 117(4.75,10.55) 118(4.25,10.55) 119(3.75,10.55) 120(3.25,10.55) 121(2.75,10.55) 122(2.25,10.55) 123(1.75,10.55) 124(1.25,10.55) 125(0.75,10.55) 126(0.25,10.55) 127(-0.25,10.55) 128(-0.75,10.55) 129(-1.25,10.55) 130(-1.75,10.55) 131(-2.25,10.55) 132(-2.75,10.55) 133(-3.25,10.55) 134(-3.75,10.55) 135(-4.25,10.55) 136(-4.75,10.55) 137(-5.25,10.55) 138(-5.75,10.55) 139(-6.25,10.55) 140(-6.75,10.55) 141(-7.25,10.55) 142(-7.75,10.55) 143(-8.25,10.55) 144(-8.75,10.55)
  silkscreen extent -10.67,-9.25 9.25,9.57, body extent -10,-10 10,10, height 1.61
UDFN-4P-1X1_MM [mm]
  round 0.1 smd mask+0: 1(-0.33,-0.508) 2(0.33,-0.508) 3(0.33,0.508) 4(-0.33,0.508)
  rrect0% 0.6x0.6 smd rot 135 mask+0: 5(0,0)
  Top Layer region: -0.224,-0.701 -0.427,-0.701 -0.427,-0.368 -0.376,-0.368 -0.224,-0.531 -0.224,-0.701
  Top Layer region: 0.218,-0.701 0.422,-0.701 0.422,-0.368 0.371,-0.368 0.218,-0.531 0.218,-0.701
  Top Layer region: 0.218,0.701 0.422,0.701 0.422,0.368 0.371,0.368 0.218,0.531 0.218,0.701
  Top Layer region: -0.224,0.701 -0.427,0.701 -0.427,0.368 -0.376,0.368 -0.224,0.531 -0.224,0.701
USB-SD-47590-001 [mm]
  rect 1.35x0.4 smd mask+0.051: 1(2.737,-1.321) 2(2.737,-0.673) 3(2.737,-0.025) 4(2.737,0.622) 5(2.737,1.27)
  oval 1.3x1.05 hole 0.65 slot 0.9 at 0 deg mask+0.064: 6(2.921,2.197) 9(2.921,-2.248)
  oval 2x1.1 / inner oval 2x1.1 / far side oval 2.2x1.4 hole 0.8 slot 1.5 at 0 deg: 7(-0.08,4.075) 8(-0.08,-4.075)
XFARMER [mil]
  rect 61x50 smd: 1(325.5,196) 2(325.5,98) 3(325.5,0) 4(325.5,-98) 5(325.5,-196) 6(-325.5,-196) 7(-325.5,-98) 8(-325.5,0) 9(-325.5,98) 10(-325.5,196)
  silkscreen extent -326,-279 326,279, body extent -350,-265 350,265, height 177
XTAL_TXC-7B [mm] "TXC"
  rect 1.2x2 smd: 1(-1.1,1.85) 2(-1.1,-1.85) 3(1.1,-1.85) 4(1.1,1.85)
  silkscreen extent -1.98,-2.7 1.8,3.15, body extent -1.67,-2.57 1.67,2.57, height 1.05

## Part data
C1 C2 C3 C9 C10 C11 C13 C21 C23 C24 C25 C26 C28 C35 C36 C37 C38 C44 C58 C64 C80 C89 C100 C114 C115 C116 C117 C118 C119 C125 C136 C155 C172: library part C0603C104K5RACTU, "CAP, CERM, 0.1uF, 50V, +/-10%, X7R, 0603"
C4 C66 C139 C178: "CAP, CERM, 0.1uF, 16V, +/-5%, X7R, 0603"
C5 C63 C164: "CAP, CERM, 1uF, 16V, +/-10%, X5R, 0603"
C6 C7 C8 C16 C29 C30 C31 C110 C111 C112 C113 C120 C121 C122: library part 06031C472KAT2A, "CAP, CERM, 4700pF, 100V, +/-10%, X7R, 0603"
C12: "CAP, AL, 10uF, 16V, +/-20%, 3 ohm, SMD"
C14 C43 C45 C53 C54 C72 C73 C76 C77: "CAP, CERM, 0.1uF, 25V, +/-5%, X7R, 0603"
C15 C17 C88 C92 C99 C126 C128 C129 C131 C132 C133 C134 C140 C141 C142 C151 C152 C154 C157 C158 C163 C165 C169 C170 C171 C173 C175: "CAP, CERM, 0.22uF, 6.3V, +/-10%, X7R, 0603"
C18: "CAP, CERM, 0.47uF, 16V, +/-10%, X7R, 0805"
C19 C33 C46 C71 C93 C149: library part GMK325AB7106MM-T, "CAP, CERM, 10uF, 35V, +/-20%, X7R, 1210"
C20 C27: library part 06033C473JAT2A, "CAP, CERM, 0.047uF, 25V, +/-5%, X7R, 0603"
C22 C83 C86 C96 C104 C124 C127 C137 C145 C147 C148 C159 C162: "CAP, CERM, 4.7uF, 6.3V, +/-10%, X5R, 0603"
C32 C34 C39 C40 C47 C57 C59 C61 C68 C75 C81 C85 C94 C97 C102 C105: library part 06031C103JAT2A, "CAP, CERM, 0.01uF, 100V, +/-5%, X7R, 0603"
C41: library part 202R18W102KV4E, "CAP, CERM, 1000pF, 2KV 10% X7R 1206"
C42 C56 C60 C62 C69 C74 C82: "CAP, CERM, 0.01uF, 100V, +/-10%, X7R, 0603"
C48 C49: "CAP, CERM, 10uF, 50V, +/-10%, X7R, 1210"
C50: "CAP, AL, 100uF, 50V, +/-20%, 0.17 ohm, TH"
C51 C52 C87: "CAP, CERM, 10uF, 16V, +/-10%, X7R, 1206"
C55 C65 C106 C107: "CAP, CERM, 27pF, 50V, +/-5%, C0G/NP0, 0603"
C67 C90 C98 C109 C177: "CAP, CERM, 0.1uF, 50V, +/-10%, X7R, 0603"
C70: "CAP, CERM, 22uF, 10V, +/-20%, X5R, 1210"
C78: "CAP, CERM, 10uF, 35V, +/-10%, X7R, 1206"
C79: "CAP, CERM, 1uF, 25V, +/-10%, X7R, 1206"
C84: "CAP, CERM, 330pF, 50V, +/-5%, C0G/NP0, 0603"
C91: "CAP, AL, 150uF, 16V, +/-20%, 0.34 ohm, SMD"
C95: "CAP, CERM, 0.039uF, 50V, +/-10%, X7R, 0603"
C101 C108: "CAP, CERM, 1uF, 10V, +/-10%, X7R, 0603"
C103 C176: "CAP, CERM, 100pF, 50V, +/-5%, C0G/NP0, 0603"
C123 C138 C143 C144 C160 C161: "CAP, CERM, 100uF, 6.3V, +/-20%, X5R, 1206"
C130: "CAP, CERM, 47pF, 25V, +/-5%, C0G/NP0, 0402"
C135: "CAP, CERM, 680pF, 25V, +/-5%, C0G/NP0, 0603"
C146: library part GRM32ER72A225KA35L, "CAP, CERM, 2.2uF, 100V, +/-10%, X7R, 1210"
C150: "CAP, CERM, 0.015uF, 16V, +/-10%, X7R, 0603"
C153 C174: "CAP, CERM, 0.1uF, 10V, +/-10%, X7R, 0603"
C156: "CAP, CERM, 0.01uF, 50V, +/-10%, X7R, 0805"
C166 C167 C168: "CAP, CERM, 47uF, 10V, +/-10%, X5R, 1210"
D1 D2: "Diode, TVS, Bi, 15V, 160W, SOD-323"
D3 D9: library part "LED_LG L29K-G2J1-24-Z", "LED SmartLED Green 570NM"
D4 D5 D10: library part "LG M47K-G1J2-24-Z", "LED SMARTLED GREEN 570NM 0603"
D6: "Rectifier, Ultrafast Power, 50V 1A"
D7: "Diode, Schottky, 40V, 3A, SMC"
D8: "Diode, Schottky, 30V, 0.2A, SOT-23"
D11 D12 D14 D15 D16 D17 D19 D20 D21 D22 D24 D25 D26 D27 D28 D29: library part BAV99WT1G, "Diode, P-N, 70V, 0.2A, SOT-323"
D13: "Diode, Ultrafast, 75V, 0.3A, SOT-23"
D18: "Diode, Schottky, 20V, 2A, SMA"
D23: "Diode, Schottky, 200V, 4A, SMC"
FB1 FB2 FB3 FB4 FB5: library part MMZ1608B102C, "FERRITE CHIP 1000 OHM 300MA 0603"
FID1 FID2 FID3 FID4 FID5 FID6 FID7 FID8: library part Fiducial, "Fiducial mark.  There is nothing to buy or mount."
J1: library part CONN_613040243121, "Connector, Right Angle, Male, 2x20 pin, 100mil spacing"
J2 J15: "Header, Male 2x5-pin, 100mil spacing"
J3: "Connector, USB Micro, Type AB"
J4: library part HSEC8-130-01-L-DV-A, "CONN HIGH SPD CARD EDGE 60 POS"
J5: library part HSEC8-160-01-L-DV-A-L, "CONN HIGH SPD CARD EDGE 120 POS"
J6 J7: "Header,  Male 10-pin, 100mil spacing,"
J8 J9 J10: library part JUMPER_2X100MIL, "Header, Male 2-pin, 100mil spacing,"
J11: library part CON_0878311420, "Cnnector Header 14Pos 2mm Vert Gold"
J12: "Header, Male 2x6 pin, 100mil spacing"
J13: "Terminal Block, 2-pin, 15-A, 5.1mm"
J14: "Connector, SMA Jack, Vertical, Gold, SMD"
L1: "Inductor, Shielded Drum Core, Ferrite, 3.3uH, 3.72A, 0.02 ohm, SMD"
LBL1: library part THT-14-423-10, "Thermal Transfer Printable Labels, 0.650\" W x 0.200\" H - 10,000 per roll"
Logo1: library part TI_Logo, "Texas Instrument Corporate Signature"
MH1 MH2 MH3 MH4: library part "NY PMS 440 0025 PH", "Mountin hole, NPTH Drill 3.2mm"
R1 R19 R20 R44 R45 R46 R47 R48 R49 R50 R51 R52 R53 R54 R55 R56 R57 R58 R59 R60 R61 R62 R63 R64 R65 R66 R67 R94 R99 R105 R106 R112 R119 R120 R133 R141 R146 R147 R154 R155 R164 R165 R174 R175 R179 R185 R189: "RES, 22 ohm, 5%, 0.063W, 0402"
R2 R3 R4 R25 R31 R35 R36: "RES, 270k ohm, 1%, 0.1W, 0603"
R5 R6 R7 R15 R16 R17 R26 R28 R32 R33 R34 R69 R70 R71: library part CRCW06034K70JNEA, "RES, 4.7k ohm, 5%, 0.1W, 0603"
R8 R13 R14 R24 R37 R38 R39: "RES, 7.50k ohm, 1%, 0.1W, 0603"
R9 R22 R43 R79 R85 R92 R102 R108 R109 R126 R130 R139 R140 R150 R158 R159 R172 R186 R192 R197 R204 R205: "RES, 0 ohm, 5%, 0.1W, 0603"
R10 R11 R12 R27 R40 R41 R42 R128 R195: "RES, 100k ohm, 1%, 0.1W, 0603"
R18 R21 R23 R68 R73 R74 R77 R83 R87 R91 R96 R107 R117 R123 R132 R138 R143 R145 R153 R160 R161 R162 R163: library part CRCW060310R0FKEA, "RES, 10.0 ohm, 1%, 0.1W, 0603"
R29 R78 R127 R136 R144 R148 R152 R166 R187 R188 R202: "RES, 4.87k ohm, 1%, 0.1W, 0603"
R30 R168: "RES, 300 ohm, 5%, 0.1W, 0603"
R72 R80 R84 R118 R137 R142 R200: "RES, 10.0k ohm, 1%, 0.1W, 0603"
R75 R76 R81 R82 R89 R90 R100 R101 R110 R111 R113 R114 R115 R124 R125 R129 R134: "RES, 100 ohm, 5%, 0.1W, 0603"
R86 R88 R201 R203 R207 R208: "RES, 4.70k ohm, 1%, 0.1W, 0603"
R93 R95 R97 R104 R116: "RES, 0 ohm, 5%, 0.063W, 0402"
R98: "RES, 1.5k ohm, 5%, 0.25W, 1206"
R103 R121 R156 R157 R194: "RES, 10k ohm, 5%, 0.1W, 0603"
R122: "RES, 150k ohm, 1%, 0.1W, 0603"
R131: "RES, 6.8 ohm, 5%, 0.25W, 1206"
R135: "RES, 49.9 ohm, 1%, 0.1W, 0603"
R149: "RES, 1.47k ohm, 1%, 0.1W, 0603"
R151: "RES, 137k ohm, 1%, 0.1W, 0603"
R167 R171: library part R-ACAS0612_SERIES, "Resistor, Chip Array, 4.7K OHM 4 RES 0612"
R169: "RES, 620 ohm, 1%, 0.1W, 0603"
R170: "RES, 17.4k ohm, 1%, 0.1W, 0603"
R173: "RES, 15k ohm, 5%, 0.1W, 0603"
R176: "RES, 47.5k ohm, 1%, 0.1W, 0603"
R177: "RES, 10.2k ohm, 1%, 0.1W, 0603"
R178: "RES, 3.24k ohm, 1%, 0.1W, 0603"
R180: "RES, 42.2k ohm, 1%, 0.1W, 0603"
R181: "RES, 58.3k ohm, 0.1%, 0.1W, 0603"
R182 R183: "RES, 0 ohm, 5%, 0.25W, 1206"
R184: "RES, 48.7k ohm, 1%, 0.1W, 0603"
R190: "RES, 14.0k ohm, 1%, 0.1W, 0603"
R191: "RES, 499 ohm, 1%, 0.1W, 0603"
R193: "RES, 4.99k ohm, 1%, 0.1W, 0603"
R196: "RES, 301 ohm, 0.5%, 0.1W, 0603"
R198: "RES, 1.00k ohm, 1%, 0.1W, 0603"
R199: "RES, 220 ohm, 1%, 0.1W, 0603"
R206: "RES, 910 ohm, 0.1%, 0.1W, 0603"
S1 S3: "Switch, Tactile, SPST-NO, 0.05A, 12V, SMT"
S2: "Switch, Slide, SPST 4 poles, SMT"
T1: library part Transformer, "Transformer"
TP1 TP2: library part TP-040_RND, "Test Point, O.040 Hole"
TP3 TP4 TP5 TP6 TP7 TP8 TP9 TP10: "Test Point, 0.020 Hole"
U1 U2 U3 U8 U13 U14 U15: "IC, 1.1nV/vHz Noise, Low Power, Precision OpAmp"
U4 U5 U6 U11 U17 U18 U19: "7 nsec, 2.7V to 5V Comparator with Rail-to- Rail Output, 5-pin SOT-23"
U7: "IC, Single Chip USB To UART Bridge"
U9: "Polyzen, 5.6V, PPTC/ZENER, SMD"
U10: library part REF30XXAIDBZ, "IC, Voltage Reference, 50ppm/°C Max, 50uA"
U12: library part REF30XXAIDBZ, "Voltage Reference, SRS PREC 4.096V SOT23-3"
U16 U21 U25 U28: "16-Bit, Quad Channel, Ultra-Low Glitch, Voltage Output DAC with 2.5V, 2ppm/°C Internal Reference, PW0016A"
U20: "IC FPGA SPARTAN, 102 I/O, 144TQFP"
U22: "Programmable 3-PLL Clock Synthesizer / Multiplier / Divider"
U23: "Buck Step Down Regulator with 3.5 to 28 V Input and 0.8 to 25 V Output, -40 to 150 degC, 8-Pin SOIC (D), Green (RoHS & no Sb/Br)"
U24: "Ultra Low Noise, 800 mA Linear Voltage Regulator for RF/Analog Circuits, DNT0012B"
U26: "Integrated 5-A 40-V Wide Input Range Boost/SEPIC/Flyback DC-DC Regulator, RTE0016C"
U27: "Single LVDS Transmitter"
U29: "Programmable 1-PLL VCXO Clock Synthesizer With 1.8-V, 2.5-V, and 3.3-V Outputs, PW0014A"
U30: "Optocoupler, 3.75kV RMS, SMT"
U31: "IC, 150mA, Low IQ, LDO Regulator"
U32: "IC, Precision Adjustable Shunt Regulator"
U33: library part DS1088LU-XX, "IC,  100MHz, EconOscillator, 2.7-3.6V, 8 uSOP"
U34 U35: "IC SRAM 512KBIT 20MHZ 8SOIC"
U36: library part TPS799XXDDC, "IC, Ultra-low Noise, High PSRR 200 mA, LDO, 1.2V 0.2A 5SOT"
U37: "IC EEPROM 1MBIT 1MHZ 8SOIC"
Y1 Y2: library part 7B-10.000MEEQ-T, "Crystal, 10.000MHz, 10pF, SMD"
ZZ1: library part AssemblyNoteLabel, "This Assembly Note is for PCB labels only"
ZZ2: library part AssemblyNote, "These assemblies are ESD sensitive, ESD precautions shall be observed."
ZZ3: library part AssemblyNote, "These assemblies must be clean and free from flux and all contaminants. Use of no clean flux is not acceptable."
ZZ4: library part AssemblyNote, "These assemblies must comply with workmanship standards IPC-A-610 Class 2, unless otherwise specified."

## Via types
v1: diameter 32, hole 16, Top Layer to Bottom Layer, tented both sides, 495 vias
v2: diameter 26, hole 12, Top Layer to Bottom Layer, tented both sides, 104 vias
v3: diameter 20, hole 8, Top Layer to Bottom Layer, tented both sides, 10 vias
v4: diameter 30, hole 16, Top Layer to Bottom Layer, tented both sides, 1 vias

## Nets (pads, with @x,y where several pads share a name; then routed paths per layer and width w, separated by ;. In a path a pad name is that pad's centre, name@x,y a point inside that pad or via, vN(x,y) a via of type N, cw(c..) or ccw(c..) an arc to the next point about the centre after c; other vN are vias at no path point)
+1.2V: C132.2 C137.1 C138.1 C142.2 C145.1 C151.2 C158.2 C171.2 FB4.2 U20.19 U20.28 U20.52 U20.89 U20.128 | length 594.8
  Top Layer w8: U20.28@3419.29,567.83 3512.83,567.83 v1(3515,570) ; U20.19@3419.29,745 v1(3494.05,745) ; v1(3765,405) 3785,385 3785.43,385 U20.52@3785.43,339.49 ; v1@3805.12,1076.65 U20.128@3805.12,1170.2 ; v1(4198.15,725.32) U20.89@4250,725.31
  Bottom Layer w8: C151.2@3470,701.5 3494.05,725.55 v1(3494.05,745) ; v1(3765,405) 3766.5,403.5 C171.2@3766.5,355 ; C132.2@3791.5,1119.02 3791.5,1090.28 v1(3807.28,1074.49) ; v1(4198.15,725.32) 4198.51,725.32 4198.82,725.63 C142.2@4198.82,773.5
+1.8V: C108.1 FB3.1 TP10.1 U31.1 | length 983.8
  Top Layer w15: FB3.1@4645.47,485.32 v1(4645.47,530)
  Bottom Layer w30: v1(4645.47,530) 4705.47,470 5130,470 5395,205 v2(5395,150)
  other v2: 5440,105 5440,150
+1.25VREF: C14.1 U4.4 U5.4 U6.4 U10.2 U11.4 U17.4 U18.4 U19.4 | length 388.1
  Top Layer w25: v1(5445,2070) 5465,2070 5487.6,2047.4 U5.4@5487.6,2022.76 ; v1(5781,1280) 5783.24,1277.76 U17.4@5818.6,1277.76 ; v1(6140,2025) 6142.24,2022.76 U6.4@6177.6,2022.76 ; v1(6471,1280) 6473.24,1277.76 U18.4@6508.6,1277.76 ; C14.1@6718.5,1865 6718.5,1811.5 U10.2@6737.5,1792.5 ; v1(6810,2030) 6812.24,2027.76 U4.4@6847.6,2027.76 ; v1(7140.31,1645) 7142.56,1642.76 U11.4@7177.91,1642.76 ; v1(7141,1280) 7143.24,1277.76 U19.4@7178.6,1277.76
  other v1: 6685,1920 6735,1920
